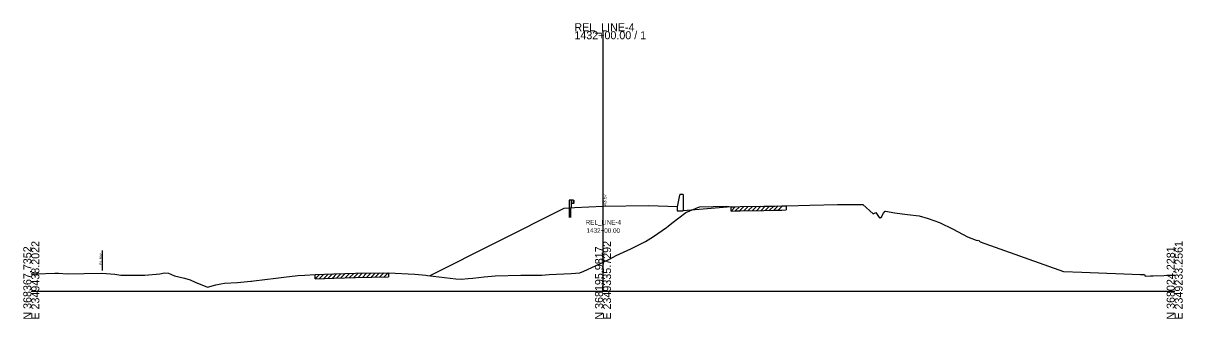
# Model space of a CAD drawing. Extents: x -26 to 2350146, y -10 to 368200.
# Drawn here: x 997.2 to 1402.8, y 6990.3 to 7093.5 of the extents above; entities that cross this region are included whole.
import ezdxf

# ---------------------------------------------------------------- set-up
doc = ezdxf.new("R2010")
doc.units = 0
for name, color, linetype in [('RD_GPK_XS_Cell', 7, 'Continuous'), ('RD_XS_EarthShd', 7, 'Continuous'), ('RD_XS_ExGround', 7, 'Continuous'), ('RD_XS_ExPaveRet', 7, 'Continuous'), ('RD_XS_ExRW', 7, 'Continuous'), ('RD_XS_GR', 7, 'Continuous'), ('RD_XS_MedBWall', 7, 'Continuous'), ('RD_XS_Pave', 7, 'Continuous'), ('RD_XS_PaveShd', 7, 'Continuous'), ('RD_XS_TieSlope', 7, 'Continuous'), ('RD_XS_TX_Elev_EX', 7, 'Continuous'), ('RD_XS_TX_Elev_PR', 7, 'Continuous'), ('RD_XS_TX_Station', 7, 'Continuous')]:
    doc.layers.add(name, color=color, linetype=linetype)

msp = doc.modelspace()

# ---------------------------------------------------------------- linework, layer by layer
at = {"layer": 'RD_GPK_XS_Cell'}
for p, q in [((1200, 7000), (1200, 7090.74)), ((1000, 7000), (1200, 7000)), ((1200, 7000), (1400, 7000))]:
    msp.add_line(p, q, dxfattribs=at)
at = {"layer": 'RD_XS_EarthShd'}
for p, q in [((1190, 7029.07), (1186.25, 7028.77)), ((1244.78, 7029.38), (1228, 7028.03))]:
    msp.add_line(p, q, dxfattribs=at)
at = {"layer": 'RD_XS_ExGround'}
msp.add_lwpolyline([(1000, 7005.99), (1001.8, 7006.03), (1008.23, 7006.24), (1009.5, 7006.24), (1012.68, 7006.01), (1018.51, 7006.09), (1024.64, 7006.22), (1029.25, 7005.88), (1031.26, 7005.54), (1038.32, 7005.51), (1039.77, 7005.5), (1044.92, 7006.02), (1046.6, 7006.36), (1047.95, 7006.27), (1050.15, 7005.33), (1053.6, 7004.44), (1055.53, 7003.92), (1057.27, 7003.13), (1061.68, 7001.35), (1064.6, 7002.15), (1066.27, 7002.54), (1067.55, 7002.72), (1072.1, 7003.01), (1076.74, 7003.48), (1077.05, 7003.5), (1077.86, 7003.6), (1085.58, 7004.5), (1088.36, 7004.83), (1093.21, 7005.42), (1095.69, 7005.56), (1099.34, 7005.74), (1105.83, 7005.96), (1113.38, 7006.19), (1125.01, 7006.35), (1134.13, 7005.85), (1138.02, 7005.5), (1138.61, 7005.45), (1148.54, 7004.28), (1150.36, 7004.09), (1152.85, 7004.35), (1154.48, 7004.5), (1158.38, 7004.93), (1162.28, 7005.3), (1171.23, 7005.49), (1171.55, 7005.49), (1177.55, 7005.5), (1178.56, 7005.53), (1181.13, 7005.73), (1188.91, 7006.16), (1191.84, 7006.41), (1193.28, 7006.93), (1197.34, 7008.85), (1200, 7010.06), (1202.25, 7011.09), (1204.62, 7012.36), (1209.73, 7014.76), (1214.91, 7017.33), (1217.64, 7019.01), (1222.22, 7022.19), (1222.75, 7022.62), (1224.07, 7023.7), (1228.93, 7027.4), (1233.76, 7029.43), (1243.31, 7029.64), (1244.78, 7029.38), (1246.12, 7029.41), (1248.01, 7029.47), (1256.26, 7029.61), (1260.13, 7029.69), (1262.53, 7029.73), (1264.06, 7029.75), (1264.27, 7029.75), (1272.4, 7029.96), (1281.98, 7030.21), (1283.41, 7030.25), (1284.82, 7030.25), (1290.26, 7030.24), (1290.9, 7030.23), (1294.47, 7027), (1295.5, 7027.37), (1296.57, 7025.63), (1296.84, 7025.49), (1297, 7025.69), (1297.36, 7025.69), (1298.17, 7027.17), (1298.69, 7027.87), (1298.86, 7027.84), (1302.04, 7027.36), (1304.62, 7026.95), (1306.49, 7026.68), (1310.64, 7026.21), (1313.76, 7025.33), (1317.72, 7023.97), (1322.48, 7021.63), (1327.48, 7018.89), (1330.52, 7017.73), (1331.12, 7017.67), (1331.48, 7017.73), (1331.64, 7017.55), (1331.94, 7017.16), (1361.08, 7006.85), (1367.51, 7006.64), (1388.05, 7005.74), (1388.48, 7005.72), (1389.39, 7005.73), (1389.68, 7005.24), (1391.58, 7005.31), (1392.42, 7005.35), (1400, 7005.5)], dxfattribs=at)
at = {"layer": 'RD_XS_ExPaveRet'}
for p, q in [((1244.78, 7027.94), (1246.25, 7029.41)), ((1244.78, 7027.94), (1244.78, 7029.38)), ((1244.78, 7027.94), (1246.12, 7027.97)), ((1246.12, 7027.97), (1248.01, 7028.03)), ((1246.28, 7027.97), (1247.77, 7029.46)), ((1247.78, 7028.02), (1249.25, 7029.49)), ((1248.01, 7028.03), (1256.26, 7028.17)), ((1249.28, 7028.05), (1250.75, 7029.51)), ((1250.78, 7028.08), (1252.25, 7029.54)), ((1252.28, 7028.1), (1253.75, 7029.56)), ((1253.78, 7028.13), (1255.25, 7029.59)), ((1255.28, 7028.15), (1256.75, 7029.62)), ((1256.26, 7028.17), (1260.13, 7028.26)), ((1256.78, 7028.18), (1258.25, 7029.65)), ((1258.28, 7028.22), (1259.75, 7029.68)), ((1259.78, 7028.25), (1261.24, 7029.71)), ((1260.13, 7028.26), (1262.53, 7028.29)), ((1261.28, 7028.27), (1262.74, 7029.73)), ((1262.53, 7028.29), (1264.06, 7028.31)), ((1264.06, 7029.75), (1264.06, 7028.31)), ((1109.84, 7004.65), (1111.32, 7006.13)), ((1111.34, 7004.69), (1112.82, 7006.17)), ((1112.84, 7004.74), (1114.3, 7006.2)), ((1114.34, 7004.76), (1115.79, 7006.22)), ((1115.84, 7004.78), (1117.29, 7006.24)), ((1117.34, 7004.81), (1118.79, 7006.26)), ((1118.84, 7004.83), (1120.29, 7006.28)), ((1120.34, 7004.85), (1121.79, 7006.3)), ((1121.84, 7004.87), (1123.29, 7006.32)), ((1123.34, 7004.89), (1124.79, 7006.34)), ((1125.01, 7006.35), (1125.01, 7004.91)), ((1099.34, 7004.3), (1100.82, 7005.79)), ((1099.34, 7004.3), (1099.34, 7005.74)), ((1099.34, 7004.3), (1105.83, 7004.53)), ((1100.84, 7004.35), (1102.32, 7005.84)), ((1102.34, 7004.41), (1103.82, 7005.89)), ((1103.84, 7004.46), (1105.32, 7005.95)), ((1105.34, 7004.51), (1106.82, 7005.99)), ((1105.83, 7004.53), (1113.38, 7004.75)), ((1106.84, 7004.56), (1108.32, 7006.04)), ((1108.34, 7004.6), (1109.82, 7006.08)), ((1113.38, 7004.75), (1125.01, 7004.91))]:
    msp.add_line(p, q, dxfattribs=at)
at = {"layer": 'RD_XS_ExRW'}
msp.add_line((1024.95, 7007.2), (1024.95, 7014.2), dxfattribs=at)
at = {"layer": 'RD_XS_GR'}
for p, q in [((1188.14, 7031.72), (1188.14, 7028.92)), ((1188.81, 7031.72), (1188.14, 7031.72)), ((1188.81, 7031.72), (1188.81, 7028.97)), ((1189.73, 7031.72), (1188.81, 7031.72)), ((1189.73, 7030.55), (1188.81, 7030.55)), ((1189.73, 7030.55), (1189.73, 7031.72)), ((1189.73, 7031.65), (1189.89, 7031.45)), ((1189.89, 7031.4), (1189.73, 7031.2)), ((1189.89, 7030.87), (1189.73, 7031.07)), ((1189.73, 7030.62), (1189.89, 7030.82)), ((1189.89, 7031.45), (1189.89, 7031.4)), ((1189.89, 7030.82), (1189.89, 7030.87)), ((1188.14, 7029.11), (1188.14, 7025.7)), ((1188.8, 7025.7), (1188.8, 7029.17))]:
    msp.add_line(p, q, dxfattribs=at)
at = {"layer": 'RD_XS_MedBWall'}
for p, q in [((1226.79, 7033.54), (1226, 7029.39)), ((1227.16, 7033.66), (1226.91, 7033.66)), ((1228, 7033.66), (1227.16, 7033.66)), ((1228, 7033.66), (1228, 7028.03)), ((1226, 7029.39), (1226, 7028.03)), ((1226, 7028.03), (1228, 7028.03))]:
    msp.add_line(p, q, dxfattribs=at)
msp.add_ellipse((1226.91, 7033.52), major_axis=(0, -0.133), ratio=0.910156, start_param=3.141593, end_param=4.607459, dxfattribs=at)
at = {"layer": 'RD_XS_Pave'}
msp.add_line((1216, 7029.79), (1200, 7029.47), dxfattribs=at)
at = {"layer": 'RD_XS_PaveShd'}
for p, q in [((1200, 7029.47), (1190, 7029.07)), ((1226, 7029.39), (1216, 7029.79))]:
    msp.add_line(p, q, dxfattribs=at)
at = {"layer": 'RD_XS_TieSlope'}
msp.add_line((1186.25, 7028.77), (1139.41, 7005.35), dxfattribs=at)

# ---------------------------------------------------------------- texts
at = {"layer": 'RD_GPK_XS_Cell'}
for s, p in [('REL_LINE-4', (1190, 7090.74)), ('1432+00.00 / 1', (1190, 7087.94))]:
    msp.add_text(s, height=2.8, dxfattribs=at).set_placement(p)
for s, p in [('N 368367.7352', (1000, 6990)), ('E 2349438.2022', (1002.8, 6990)), ('N 368195.9817', (1200, 6990)), ('E 2349335.7292', (1202.8, 6990)), ('N 368024.2281', (1400, 6990)), ('E 2349233.2561', (1402.8, 6990))]:
    msp.add_text(s, height=2.8, rotation=90, dxfattribs=at).set_placement(p)
at = {"layer": 'RD_XS_ExRW'}
msp.add_text('EX. R/W ', height=0.75, rotation=90, dxfattribs=at).set_placement((1024.7, 7009.15))
at = {"layer": 'RD_XS_TX_Elev_EX'}
msp.add_text('24.06', height=1, rotation=90, dxfattribs=at).set_placement((1200.5, 7010.06))
at = {"layer": 'RD_XS_TX_Elev_PR'}
msp.add_text(' 43.57', height=1.2, rotation=90, dxfattribs=at).set_placement((1201.2, 7029.33))
at = {"layer": 'RD_XS_TX_Station'}
for s, p in [('REL_LINE-4', (1193.93, 7023.23)), ('1432+00.00', (1194.23, 7020.33))]:
    msp.add_text(s, height=1.6, dxfattribs=at).set_placement(p)

doc.saveas('drawing.dxf')
